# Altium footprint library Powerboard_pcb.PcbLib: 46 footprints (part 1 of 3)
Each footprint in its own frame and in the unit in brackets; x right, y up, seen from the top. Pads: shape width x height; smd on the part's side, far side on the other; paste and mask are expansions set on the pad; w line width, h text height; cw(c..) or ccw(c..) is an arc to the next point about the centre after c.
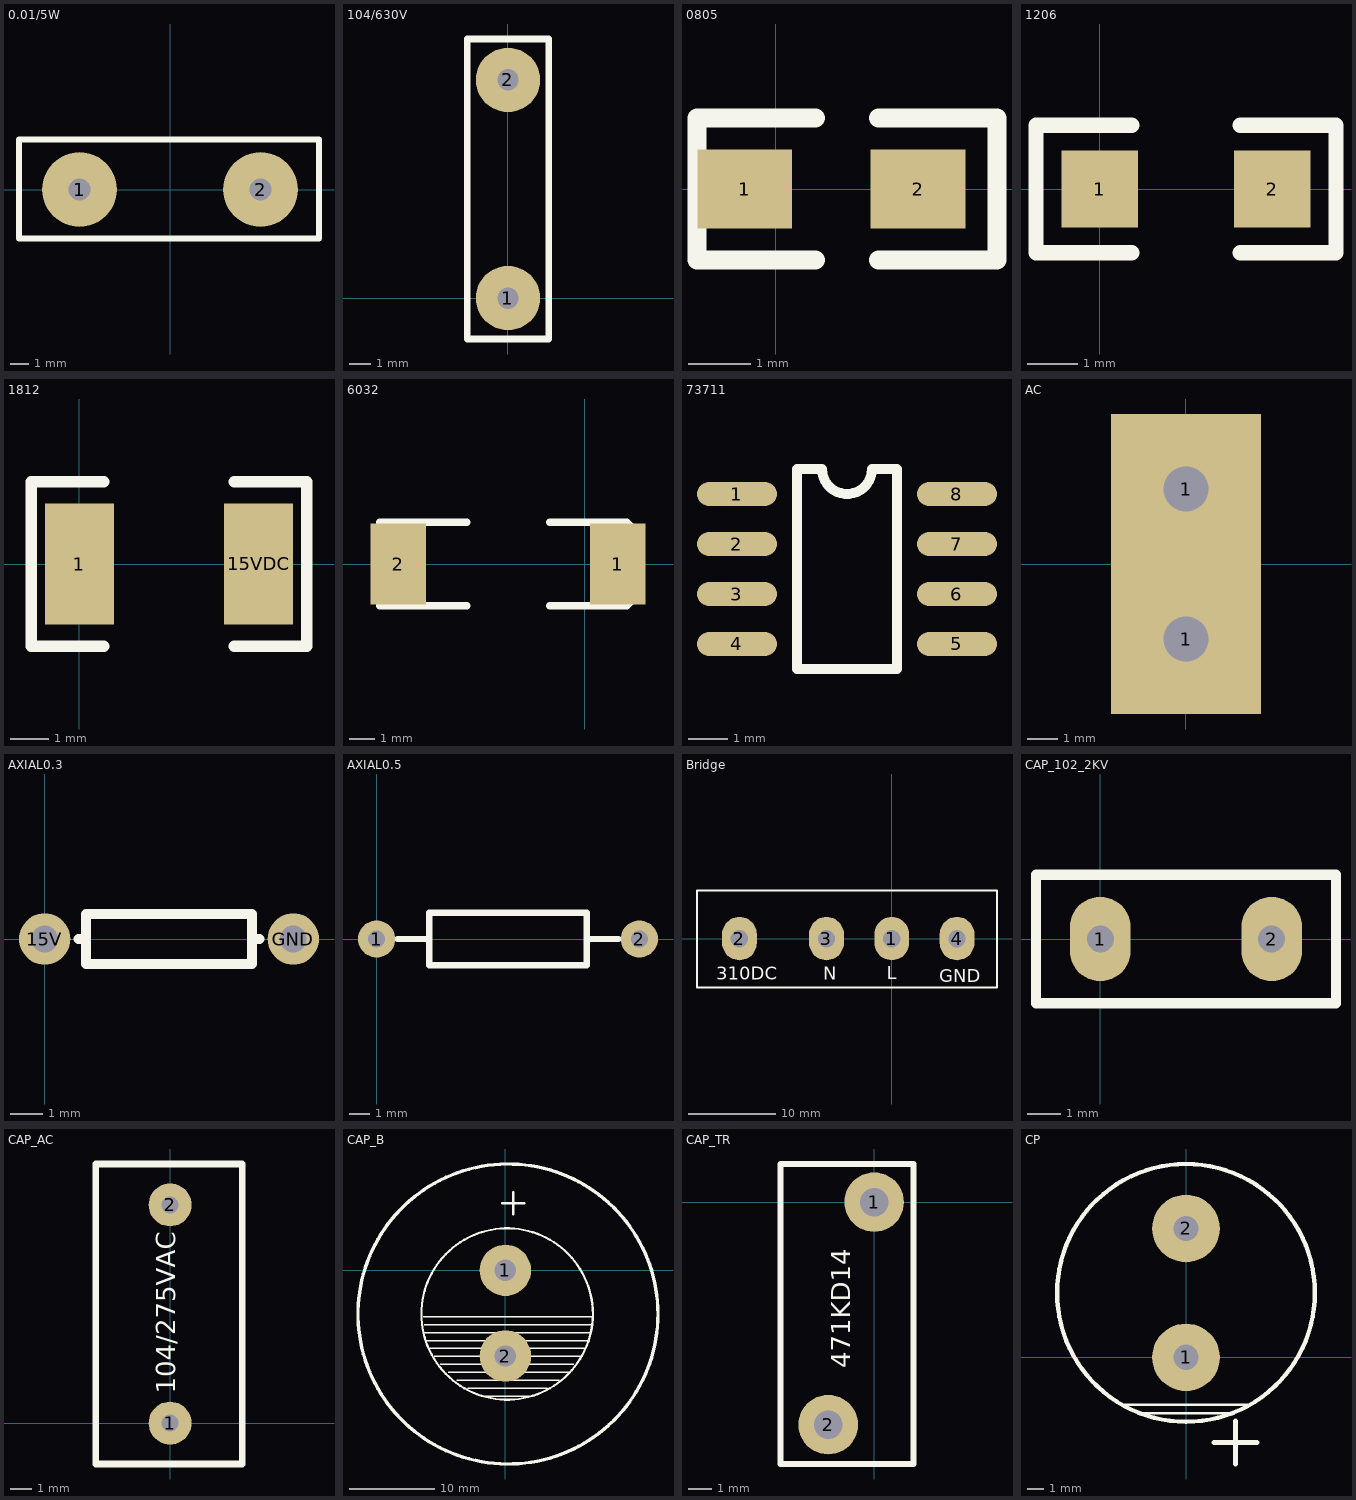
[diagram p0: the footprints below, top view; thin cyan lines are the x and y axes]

## 0.01/5W [mm]
pads (2):
  round 4 hole 1.2: 1(-4.85,0) 2(4.85,0)
Top Overlay:
  lines w0.305: -8.095,-2.625 -8.095,2.683 7.983,2.683 7.983,-2.625 -8.095,-2.625

## 104/630V [mm]
pads (2):
  round 3 hole 1: 1(0,0) 2(0,10.16)
Top Overlay:
  lines w0.305: -1.905,-1.905 -1.905,12.065 1.905,12.065 1.905,-1.905 -1.905,-1.905

## 0805 [mil]
pads (2):
  rect 60x50 smd: 1(-19.68,0) 2(90,0)
Top Overlay:
  lines w12: 25,-45 -50,-45 -50,45 25,45 ; 65,-45 140,-45 140,45 65,45

## 1206 [mil]
pads (2):
  rect 60x60 smd: 1(0,0) 2(135,0)
Top Overlay:
  lines w12: 25,-50 -50,-50 -50,50 25,50 ; 110,-50 185,-50 185,50 110,50

## 1812 [mm]
pads (2):
  rect 1.8x3.175 smd: 1(0,0) 15VDC(4.699,0)
Top Overlay:
  lines w0.305: 0.635,-2.159 -1.27,-2.159 -1.27,2.159 0.635,2.159 ; 4.064,-2.159 5.969,-2.159 5.969,2.159 4.064,2.159

## 6032 [mm]
pads (2):
  rect 2.2x3.2 smd: 1(1.3,0) 2(-7.4,0)
Top Overlay:
  lines w0.305: -4.699,-1.651 -8.128,-1.651 -8.128,1.651 -4.699,1.651 ; -1.397,-1.651 1.651,-1.651 2.159,-1.143 2.159,1.143 1.651,1.651 -1.397,1.651

## 73711 [mil]
pads (8):
  oval 80x24 smd: 1(333.3,-263.06) 2(333.3,-313.06) 3(333.3,-363.06) 4(333.3,-413.06) 5(553.3,-413.06) 6(553.3,-363.06) 7(553.3,-313.06) 8(553.3,-263.06)
Top Overlay:
  lines w10: 393.3,-438.06 493.3,-438.06 493.3,-238.06 468.3,-238.06 cw(c443.3,-238.06) 418.3,-238.06 393.3,-238.06 393.3,-438.06

## AC [mm]
pads (2):
  rect 5x5 hole 1.5: 1(0,-2.5) 1(0,2.5)

## AXIAL0.3 [mil]
pads (2):
  round 62 hole 32: 15V(0,0) GND(300,0)
Top Overlay:
  lines w12: 41,0 50,0 ; 259,0 250,0 ; 250,0 250,-30 50,-30 50,30 250,30 250,0

## AXIAL0.5 [mm]
pads (2):
  round 1.8 hole 0.813: 1(0,0) 2(12.7,0)
Top Overlay:
  lines w0.305: 1.016,0 2.54,0 ; 10.16,0 11.684,0 ; 2.54,-1.27 2.54,1.27 10.16,1.27 10.16,-1.27 2.54,-1.27

## Bridge [mm]
pads (4):
  oval 4x5 hole 2: 1(0,0) 2(-17.5,0) 3(-7.5,0) 4(7.5,0)
Bottom Layer:
  lines w0.254: -19.4,0.46 -19.3,0.56
Top Overlay:
  lines w0.254: -22.377,-5.639 -22.377,5.537 12.09,5.537 12.09,-5.639 -22.377,-5.639
  text "GND" at 5.436,-5.029 h1.52
  text "310DC" at -20.168,-4.75 h1.52
  text "N" at -7.874,-4.75 h1.52
  text "L" at -0.584,-4.674 h1.52

## CAP_102_2KV [mm]
pads (2):
  oval 1.8x2.5 hole 0.8: 1(0,0) 2(5.08,0)
Top Overlay:
  lines w0.305: -1.905,-1.905 -1.905,1.905 6.985,1.905 6.985,-1.905 -1.905,-1.905

## CAP_AC [mm] "104/275VAC"
pads (2):
  round 2 hole 0.8: 1(0,0) 2(0,10.16)
Top Overlay:
  lines w0.305: -3.454,-1.905 -3.454,12.065 3.353,12.065 3.353,-1.905 -3.454,-1.905
  text "104/275VAC" at 0.531,1.369 h1.52

## CAP_B [mm]
pads (2):
  round 6 hole 2.5: 1(0,0) 2(0,-10)
Top Overlay:
  circle w0.254: c0.2,-5.1 r10
  circle w0.4: c0.3,-5.1 r17.5
  lines w0.15: -9.593,-5.4 10.3,-5.4 ; -9.588,-7.262 10.095,-7.262 ; -9.483,-6.331 10.2,-6.331 ; -9.188,-8.194 9.812,-8.194 ; -8.888,-9.125 9.4,-9.125 ; -8.288,-10.056 9,-10.056 ; -7.588,-10.987 8,-10.987 ; -6.688,-11.918 7.4,-11.918 ; -5.688,-12.85 6.3,-12.85 ; -4.388,-13.781 4.9,-13.781 ; -2.688,-14.712 3,-14.712
  lines w0.305: -0.37,7.8 2.17,7.8 ; 0.9,6.53 0.9,9.07

## CAP_TR [mm]
pads (2):
  round 2.5 hole 1.2: 1(0,0) 2(-1.93,-9.347)
Top Layer:
  lines w0.254: -1.963,-8.591 -1.93,-9.347 -1.913,-8.687
Top Overlay:
  lines w0.254: -3.937,-10.998 -3.937,1.6 1.651,1.6 1.651,-10.998 -3.937,-10.998
  text "471KD14" at -1.014,-6.987 h0.8

## CP [mm]
pads (2):
  round 4 hole 1.5: 1(0,0) 2(0,7.62)
Top Overlay:
  circle w0.254: c0,3.81 r7.62
  lines w0.15: -3.759,-2.801 3.683,-2.801 ; -2.845,-3.309 2.667,-3.309
  lines w0.305: 1.651,-5.037 4.191,-5.037 ; 2.921,-6.307 2.921,-3.767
